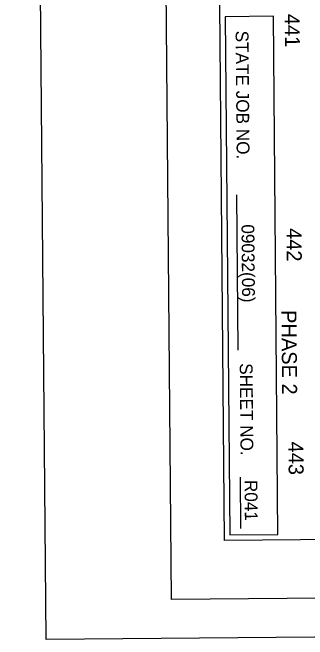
# Model space of a CAD drawing. Extents: x 2149873 to 2152007, y 140538 to 142349.
# Drawn here: x 2149872.9 to 2150010.8, y 140538.2 to 140831.5 of the extents above; entities that cross this region are included whole.
import ezdxf

# ---------------------------------------------------------------- set-up
doc = ezdxf.new("R2010")
doc.units = 0
for name, color, linetype in [('SHT_Plan_Profile_Sheet_Sta_Txt', 7, 'Continuous'), ('SHT_Plan_Profile_Sheet_Txt', 7, 'Continuous'), ('SHT_Plot_Shape_Full', 7, 'Continuous'), ('SHT_Plot_Shape_Half', 7, 'Continuous'), ('SHT_Sheet_Border', 7, 'Continuous'), ('SHT_Standard_Sheet_Lines', 7, 'Continuous')]:
    doc.layers.add(name, color=color, linetype=linetype)

msp = doc.modelspace()

# ---------------------------------------------------------------- linework, layer by layer
at = {"layer": 'SHT_Plot_Shape_Full'}
msp.add_lwpolyline([(2151072.86, 142348.62), (2151088.62, 140548.69), (2149888.66, 140538.18), (2149872.91, 142338.11)], close=True, dxfattribs=at)
at = {"layer": 'SHT_Plot_Shape_Half'}
msp.add_lwpolyline([(2151032.33, 142266.38), (2151047.21, 140566.45), (2149947.25, 140556.82), (2149932.37, 142256.76)], close=True, dxfattribs=at)
at = {"layer": 'SHT_Sheet_Border'}
for points in [[(2151008.19, 142168.67), (2151021.97, 140593.73), (2149972.01, 140584.54), (2149958.23, 142159.48)], [(2149994.87, 140829.75), (2149972.37, 140829.55), (2149974.49, 140587.06), (2149996.99, 140587.26)]]:
    msp.add_lwpolyline(points, close=True, dxfattribs=at)
at = {"layer": 'SHT_Standard_Sheet_Lines'}
for p, q in [((2149977.53, 140746.17), (2149978.17, 140673.47)), ((2149979.25, 140614.17), (2149979.46, 140590.04))]:
    msp.add_line(p, q, dxfattribs=at)

# ---------------------------------------------------------------- texts
at = {"layer": 'SHT_Plan_Profile_Sheet_Sta_Txt'}
for s, p in [('441', (2150000.11, 140830.87)), ('442', (2150000.99, 140730.6)), ('443', (2150001.86, 140630.74))]:
    msp.add_text(s, height=7, rotation=270.5015, dxfattribs=at).set_placement(p)
at = {"layer": 'SHT_Plan_Profile_Sheet_Txt'}
for s, height, p in [('STATE JOB NO.', 6, (2149977.17, 140822.99)), ('09032(06)', 6, (2149979.91, 140732.38)), ('PHASE 2', 7, (2149998.6, 140692.24)), ('SHEET NO.', 6, (2149979.1, 140667.4)), ('R041', 6, (2149981.34, 140612.82))]:
    msp.add_text(s, height=height, rotation=270.5015, dxfattribs=at).set_placement(p)

doc.saveas('drawing.dxf')
